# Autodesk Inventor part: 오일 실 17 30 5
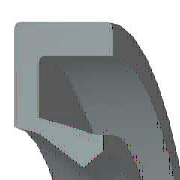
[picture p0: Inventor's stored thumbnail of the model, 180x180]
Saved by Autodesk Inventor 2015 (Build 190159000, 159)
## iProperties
Created: 2012-02
Part Number: 오일 실 17 30 5
Material: 고무
Description: 오일 실 - 스프링 장착, 비스프링, 고무 덮개 G
Document SubType Name: Modeling
Standard: JIS B 2402
Designer: mduedu
Standards Organization: JIS
Language: ko-KR
Size Designation: 17 30 5 A
Categories: <MemberInstance><Categories><Category DisplayName="샤프트 부품" InternalName="7f7aeb1f-a693-4053-b835-cee3144e0d98" Mnemonic="SHFT"><Category DisplayName="실링" Intern
Density: 0.93 g/cm^3
Appearance: 고무 - 검은색 - 버전 1.1
IsCustomPart: 1
Author: mduedu
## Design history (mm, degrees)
body "Solid1"
revolve "회전1" stored, may be unused: angle "d29" = 360 deg
chamfer "모따기1" distance "d30" = 0.25 (= 0.05 x b); stored, may be unused: second distance "d31" = 0.5 (= 0.1 x b), angle "d39" = 45 deg
chamfer "모따기2" distance "d32" = 0.5 (= 0.1 x b); stored, may be unused: second distance "d33" = 0.25 (= 0.05 x b), angle "d40" = 45 deg
fillet "모깎기1" dims "d34" = 0.25 (= 0.05 x b)
sketch "스케치2"
  geometry: L1 (9.58, -3.438)-(9.905, -5); L2 (9.147, -3.282)-(9.58, -3.438); L3 (8.5, -1.72)-(9.147, -3.282); L4 (9.682, -1.22)-(8.5, -1.72); L5 (10.811, -3.75)-(9.682, -1.22); L6 (12.111, -3.75)-(10.811, -3.75); L7 (13.556, -1.25)-(12.111, -3.75); L8 (13.556, 0)-(13.556, -1.25); L9 (15, 0)-(13.556, 0); L10 (15, -5)-(15, 0); L11 (9.905, -5)-(15, -5); L12 (0, -9.6)-(0, 1.6) reference; L13 (28, 0)-(14, 0) reference
  constraints: 22 end point, 3 horizontal, 2 vertical
  dimensions: "d2" = 5 distance of L10.start L9.start (= b); "d4" = 1.25 vertical distance of L5.start L1.end (= 0.25 x b); "d6" = 1.44444 distance of L9.start L8.start (= 0.111111 x dd - 0.111111 x Diam); "d8" = 1.25 distance of L8.start L7.start (= 0.25 x b); "d10" = 1.44444 horizontal distance of L7.start L6.start (= 0.111111 x dd - 0.111111 x Diam); "d12" = 1.21951 vertical distance of L9.start L4.start (= 0.243902 x b); "d14" = 1.18182 horizontal distance of L4.start L3.start (= 0.0909091 x dd - 0.0909091 x Diam); "d16" = 0.5 vertical distance of L4.start L3.start (= 0.1 x b); "d18" = 1.3 distance of L6.start L5.start (= 0.1 x dd - 0.1 x Diam); "d20" = 1.5625 vertical distance of L3.start L2.start (= 0.3125 x b); "d22" = 0.64677 horizontal distance of L3.start L2.start (= 0.0497512 x dd - 0.0497512 x Diam); "d24" = 0.325 horizontal distance of L1.start L1.end (= 0.025 x dd - 0.025 x Diam); "d26" = 1.5625 vertical distance of L1.start L1.end (= 0.3125 x b); "d28" = 0.43333 horizontal distance of L2.start L1.start (= 0.0333333 x dd - 0.0333333 x Diam); "d35" = 0 distance between parallel lines of L13 L9; "d36" = 15 distance between parallel lines of L12 L10 (= 0.5 x dd); "d37" = 8.5 distance from line of L12 L3.start (= 0.5 x Diam)
other parameters: "Diam" = 17 [user parameter; used in 8 equation terms], "b" = 5 [user parameter; used in 12 equation terms], "d1" = 8 (derived), "d3" = 2 (derived), "d5" = 2.22222 (derived), "d7" = 2 (derived), "d9" = 2.22222 (derived), "d11" = 1.95122 (derived), "d13" = 1.81818 (derived), "d15" = 0.8 (derived), "d17" = 2 (derived), "d19" = 2.5 (derived), "d21" = 0.99502 (derived), "d23" = 0.5 (derived), "d25" = 2.5 (derived), "d27" = 0.66667 (derived), "d38" = 0
